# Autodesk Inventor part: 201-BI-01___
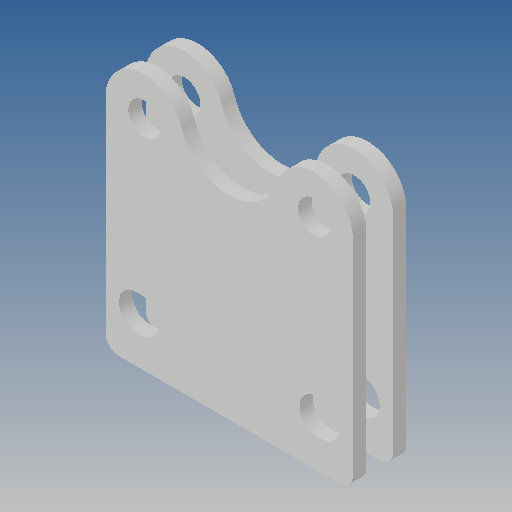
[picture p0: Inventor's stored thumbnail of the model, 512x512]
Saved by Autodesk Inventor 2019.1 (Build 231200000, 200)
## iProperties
Created: 2010-06
Part Number: 201-BI-01___
Material: Ogólny
Document SubType Name: Modeling
Designer: CADENGINEERING4
Density: 1 g/cm^3
Appearance: Domyślna
Author: CADENGINEERING4
Revision Number: ANY
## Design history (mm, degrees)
feature "NONE"
feature "NONE:1"
node "Bryła1"
node "Bryła2"
